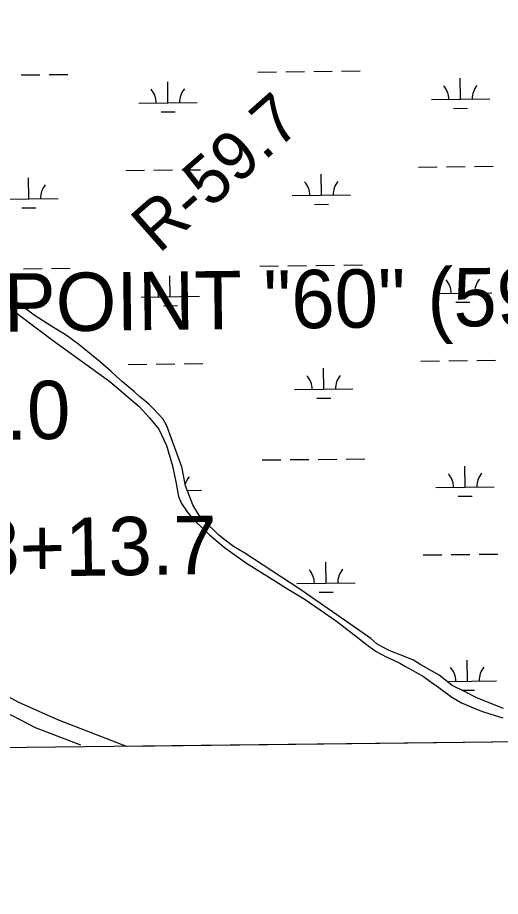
# Model space of a CAD drawing. Extents: x 3694830 to 3732949, y 415201 to 440970.
# Drawn here: x 3720431 to 3721259, y 420616 to 422124 of the extents above; entities that cross this region are included whole.
import ezdxf

# ---------------------------------------------------------------- set-up
doc = ezdxf.new("R2010")
doc.units = 0
for name, color, linetype in [('V-CHAN-NAID', 7, 'Continuous'), ('V-GRID-FRAM', 7, 'Continuous'), ('V-RIVR-RANG-IDEN', 7, 'Continuous'), ('V-ROAD-CNTR', 7, 'Continuous'), ('V-SITE-VEGE', 7, 'Continuous'), ('V-SURV-IDEN', 7, 'Continuous'), ('V-WETL-SWMP', 7, 'Continuous')]:
    doc.layers.add(name, color=color, linetype=linetype)

msp = doc.modelspace()

# ---------------------------------------------------------------- linework, layer by layer
at = {"layer": 'V-GRID-FRAM'}
msp.add_lwpolyline([(3698844.7, 438797.5), (3730590.8, 439176.2), (3730815.6, 420995.1), (3699053.6, 420616.3), (3698844.7, 438797.5)], dxfattribs=at)
at = {"layer": 'V-ROAD-CNTR'}
msp.add_lwpolyline([(3718947.5, 424793.9), (3718964, 424411.4), (3718982.2, 424062.3), (3719015.2, 423758.3), (3719087.3, 423283.5), (3719154, 422831.8), (3719191.5, 422587.8), (3719255.9, 422328.3), (3719350.6, 422063.9), (3719444.2, 421874.4), (3719568.8, 421676.5), (3719728.1, 421465.7), (3719881.2, 421306.9), (3720024.6, 421178.6), (3720151.9, 421084.4), (3720292.9, 420993.4), (3720460.7, 420905.9), (3720538.9, 420876)], dxfattribs=at)
at = {"layer": 'V-SITE-VEGE'}
for p, q in [((3720405, 421634.9), (3720492.3, 421569)), ((3720492.3, 421569), (3720589.2, 421499.4)), ((3720589.2, 421499.4), (3720639.1, 421456.5)), ((3720639.1, 421456.5), (3720657.3, 421437.2)), ((3720657.3, 421437.2), (3720672.8, 421417.4)), ((3720672.8, 421417.4), (3720686.2, 421389.6)), ((3720686.2, 421389.6), (3720696.4, 421354.7)), ((3720696.4, 421354.7), (3720702.8, 421324.2)), ((3720702.8, 421324.2), (3720706.5, 421302.2)), ((3720706.5, 421302.2), (3720711.9, 421289.9)), ((3720711.9, 421289.9), (3720722.6, 421274.4)), ((3720722.6, 421274.4), (3720735.5, 421259.9)), ((3720735.5, 421259.9), (3720760.1, 421236.3)), ((3720760.1, 421236.3), (3720785.8, 421214.9)), ((3720785.8, 421214.9), (3720823.3, 421187.6)), ((3720823.3, 421187.6), (3720867.2, 421160.2)), ((3720867.2, 421160.2), (3720894, 421143.6)), ((3720894, 421143.6), (3720922.4, 421126.5)), ((3720922.4, 421126.5), (3720949.7, 421107.7)), ((3720949.7, 421107.7), (3720977.6, 421088.5)), ((3720977.6, 421088.5), (3721015.6, 421059)), ((3721015.6, 421059), (3721029, 421048.3)), ((3721029, 421048.3), (3721045.6, 421036.5)), ((3721045.6, 421036.5), (3721062.8, 421027.4)), ((3721062.8, 421027.4), (3721075.6, 421021.5)), ((3721075.6, 421021.5), (3721086.3, 421016.1)), ((3721086.3, 421016.1), (3721096, 421010.8)), ((3721096, 421010.8), (3721108.8, 421003.8)), ((3721108.8, 421003.8), (3721127.1, 420993.6)), ((3720431.9, 420949.5), (3720373.7, 420981.4)), ((3721127.1, 420993.6), (3721140.4, 420984)), ((3721140.4, 420984), (3721151.2, 420976.5)), ((3721151.2, 420976.5), (3721175.3, 420958.3)), ((3720499.9, 420919.3), (3720431.9, 420949.5)), ((3721175.3, 420958.3), (3721192.4, 420948.1)), ((3721192.4, 420948.1), (3721210.1, 420940.6)), ((3721210.1, 420940.6), (3721226.7, 420934.1)), ((3720612, 420875.6), (3720499.9, 420919.3)), ((3721226.7, 420934.1), (3721242.2, 420928.8)), ((3721242.2, 420928.8), (3721263.1, 420922.3)), ((3720617.9, 420873.5), (3720612, 420875.6)), ((3721349.5, 420882.2), (3720617.9, 420873.5))]:
    msp.add_line(p, q, dxfattribs=at)
at = {"layer": 'V-WETL-SWMP'}
for p, q in [((3720436.7, 422025.3), (3720468.7, 422025.6)), ((3720484.7, 422025.8), (3720516.7, 422026.2)), ((3720842.6, 422030.1), (3720874.6, 422030.5)), ((3720890.6, 422030.7), (3720922.6, 422031)), ((3720938.6, 422031.2), (3720970.6, 422031.6)), ((3720986.6, 422031.8), (3721018.6, 422032.2)), ((3720688.6, 421977.5), (3720688.2, 422013.5)), ((3721190.5, 421983.5), (3721190, 422019.5)), ((3720638.6, 421976.9), (3720738.6, 421978.1)), ((3721140.5, 421982.9), (3721240.5, 421984.1)), ((3720676.8, 421961.9), (3720700.8, 421962.2)), ((3721178.7, 421967.9), (3721202.7, 421968.2)), ((3720616.6, 421861.2), (3720648.6, 421861.6)), ((3720664.6, 421861.8), (3720696.6, 421862.2)), ((3720712.6, 421862.4), (3720744.6, 421862.7)), ((3720952, 421818.8), (3720951.5, 421854.8)), ((3721118.4, 421867.2), (3721150.4, 421867.6)), ((3721166.4, 421867.8), (3721198.4, 421868.2)), ((3721214.4, 421868.3), (3721246.4, 421868.7)), ((3720450.1, 421812.8), (3720449.6, 421848.8)), ((3720400.1, 421812.2), (3720500.1, 421813.4)), ((3720902, 421818.2), (3721001.9, 421819.4)), ((3720438.3, 421797.2), (3720462.3, 421797.5)), ((3720940.1, 421803.2), (3720964.1, 421803.5)), ((3720440.7, 421692.6), (3720472.7, 421693)), ((3720488.7, 421693.2), (3720520.7, 421693.6)), ((3720846.5, 421697.4), (3720878.5, 421697.8)), ((3720894.5, 421698), (3720926.5, 421698.4)), ((3720942.5, 421698.6), (3720974.5, 421699)), ((3720990.5, 421699.2), (3721022.5, 421699.5)), ((3720692.6, 421644.9), (3720692.1, 421680.9)), ((3721194.4, 421650.8), (3721194, 421686.8)), ((3720431.5, 421633.6), (3720415, 421646.1)), ((3720642.6, 421644.3), (3720742.6, 421645.5)), ((3721144.4, 421650.2), (3721244.4, 421651.4)), ((3720459, 421613.1), (3720431.5, 421633.6)), ((3720680.8, 421629.3), (3720704.8, 421629.6)), ((3721182.6, 421635.3), (3721206.6, 421635.6)), ((3720489.5, 421593.9), (3720459, 421613.1)), ((3720514.1, 421578.8), (3720489.5, 421593.9)), ((3720536, 421563.1), (3720514.1, 421578.8)), ((3720572.8, 421532.3), (3720536, 421563.1)), ((3720591.4, 421516.6), (3720572.8, 421532.3)), ((3720620.5, 421528.6), (3720652.5, 421528.9)), ((3720668.5, 421529.1), (3720700.5, 421529.5)), ((3720716.5, 421529.7), (3720748.5, 421530.1)), ((3721122.4, 421534.5), (3721154.4, 421534.9)), ((3721170.4, 421535.1), (3721202.4, 421535.5)), ((3721218.4, 421535.7), (3721250.4, 421536.1)), ((3720599.8, 421508.8), (3720591.4, 421516.6)), ((3720610.9, 421499.1), (3720599.8, 421508.8)), ((3720955.9, 421486.1), (3720955.5, 421522.1)), ((3720621.7, 421489.9), (3720610.9, 421499.1)), ((3720631.1, 421481.5), (3720621.7, 421489.9)), ((3720640.6, 421473.1), (3720631.1, 421481.5)), ((3720905.9, 421485.5), (3721005.9, 421486.7)), ((3720648.4, 421466.6), (3720640.6, 421473.1)), ((3720655.7, 421460.7), (3720648.4, 421466.6)), ((3720944.1, 421470.6), (3720968.1, 421470.8)), ((3720663.3, 421453.1), (3720655.7, 421460.7)), ((3720673.3, 421443.1), (3720663.3, 421453.1)), ((3720680.3, 421434.7), (3720673.3, 421443.1)), ((3720686.5, 421423.4), (3720680.3, 421434.7)), ((3720692.7, 421407.2), (3720686.5, 421423.4)), ((3720712.4, 421352.9), (3720692.7, 421407.2)), ((3720850.5, 421364.8), (3720882.5, 421365.2)), ((3720898.5, 421365.4), (3720930.5, 421365.7)), ((3720946.5, 421365.9), (3720978.5, 421366.3)), ((3720994.5, 421366.5), (3721026.5, 421366.9)), ((3720718.7, 421320.2), (3720712.4, 421352.9)), ((3721198.4, 421318.2), (3721198, 421354.2)), ((3720731.1, 421287.7), (3720718.7, 421320.2)), ((3720721.6, 421312.5), (3720746.5, 421312.8)), ((3721148.4, 421317.6), (3721248.4, 421318.8)), ((3721186.6, 421302.6), (3721210.6, 421302.9)), ((3720741.9, 421270.7), (3720731.1, 421287.7)), ((3720750.5, 421261), (3720741.9, 421270.7)), ((3720776.2, 421235.9), (3720750.5, 421261)), ((3720786.7, 421227.2), (3720776.2, 421235.9)), ((3720801.3, 421216.7), (3720786.7, 421227.2)), ((3720820.8, 421204.8), (3720801.3, 421216.7)), ((3720914.8, 421143.4), (3720820.8, 421204.8)), ((3721126.4, 421201.9), (3721158.4, 421202.3)), ((3721174.4, 421202.5), (3721206.4, 421202.8)), ((3721222.4, 421203), (3721254.4, 421203.4)), ((3720959.9, 421153.5), (3720959.5, 421189.5)), ((3720909.9, 421152.9), (3721009.9, 421154.1)), ((3720991.3, 421089.9), (3720914.8, 421143.4)), ((3720948.1, 421137.9), (3720972.1, 421138.2)), ((3721036.7, 421058.6), (3720991.3, 421089.9)), ((3721046.7, 421049.6), (3721036.7, 421058.6)), ((3721055, 421044.8), (3721046.7, 421049.6)), ((3721067.2, 421038.8), (3721055, 421044.8)), ((3721075, 421035.3), (3721067.2, 421038.8)), ((3721086.7, 421030.7), (3721075, 421035.3)), ((3721097.2, 421026.7), (3721086.7, 421030.7)), ((3721109.9, 421021.3), (3721097.2, 421026.7)), ((3721122.3, 421013.7), (3721109.9, 421021.3)), ((3721153.9, 420995.6), (3721122.3, 421013.7)), ((3721202.4, 420985.5), (3721201.9, 421021.5)), ((3721176.1, 420978.3), (3721153.9, 420995.6)), ((3721167.3, 420985.1), (3721252.4, 420986.1)), ((3721197.4, 420967.5), (3721176.1, 420978.3)), ((3721192.5, 420970), (3721214.6, 420970.3)), ((3721219.6, 420956.4), (3721197.4, 420967.5)), ((3721264.2, 420938.8), (3721219.6, 420956.4))]:
    msp.add_line(p, q, dxfattribs=at)
for centre, start, end in [((3721135.2, 421983.3), 359.9115, 41.4552), ((3721245.7, 421984.6), 139.9115, 181.4552), ((3720633.4, 421977.3), 359.9115, 41.4552), ((3720743.8, 421978.6), 139.9115, 181.4552), ((3720896.7, 421818.6), 359.9115, 41.4552), ((3721007.2, 421819.9), 139.9115, 181.4552), ((3720505.3, 421813.9), 139.9115, 181.4552), ((3721139.2, 421650.7), 359.9115, 41.4552), ((3721249.7, 421652), 139.9115, 181.4552), ((3720637.3, 421644.7), 359.9115, 41.4552), ((3720747.8, 421646), 139.9115, 181.4552), ((3720900.7, 421485.9), 359.9115, 41.4552), ((3721011.2, 421487.3), 139.9115, 181.4552), ((3721253.6, 421319.3), 139.9115, 181.4552), ((3720751.8, 421313.3), 139.9115, 163.2502), ((3721143.2, 421318), 359.9115, 41.4552), ((3720904.6, 421153.3), 359.9115, 41.4552), ((3721015.1, 421154.6), 139.9115, 181.4552), ((3721147.1, 420985.4), 359.9115, 41.4552), ((3721257.6, 420986.7), 139.9115, 181.4552)]:
    msp.add_arc(centre, 35.2, start, end, dxfattribs=at)

# ---------------------------------------------------------------- texts
at = {"layer": 'V-CHAN-NAID'}
msp.add_text('POVERTY POINT "60" (59.9)', height=100, rotation=0.6762, dxfattribs=at).set_placement((3719731.4, 421576.6))
at = {"layer": 'V-RIVR-RANG-IDEN'}
msp.add_text('R-59.7', height=83, rotation=41.4181, dxfattribs=at).set_placement((3720673.1, 421717.4))
at = {"layer": 'V-SURV-IDEN'}
for s, rotation, p in [('1124+49.0', 1.0703, (3719886.5, 421389.5)), ('1128+13.7', 0.8662, (3720137.5, 421159.9))]:
    msp.add_text(s, height=100, rotation=rotation, dxfattribs=at).set_placement(p)

doc.saveas('drawing.dxf')
